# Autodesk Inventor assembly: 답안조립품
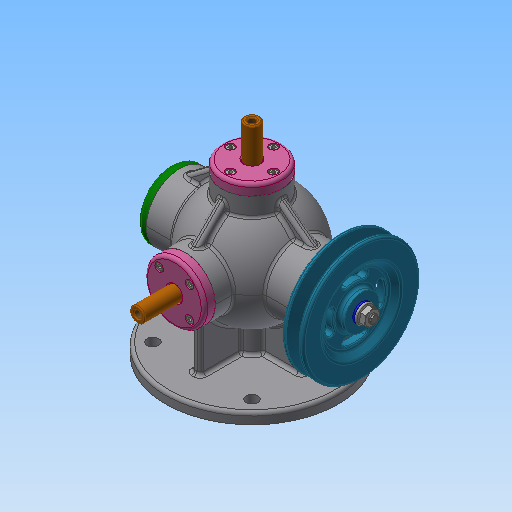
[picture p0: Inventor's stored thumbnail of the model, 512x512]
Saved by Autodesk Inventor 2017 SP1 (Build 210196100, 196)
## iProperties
Part Number: 답안조립품
Material: 일반
Document SubType Name: Assembly
Designer: MRC
Author: MRC
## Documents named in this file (17)
- C:\Users\MRC\Desktop\620909V1006\답안조립품.iam
- C:\Users\MRC\Desktop\620909V1006\본체.ipt
- C:\Users\MRC\Desktop\620909V1006\V-벨트풀리.ipt
- C:\Users\MRC\Desktop\620909V1006\가변스프링1.ipt
- C:\Users\MRC\Desktop\620909V1006\가변스프링2.ipt
- C:\Users\MRC\Desktop\620909V1006\너트-M8x1.ipt
- C:\Users\MRC\Desktop\620909V1006\뒤커버.ipt
- C:\Users\MRC\Desktop\620909V1006\베어링- 6202.ipt
- C:\Users\MRC\Desktop\620909V1006\본체커버.ipt
- C:\Users\MRC\Desktop\620909V1006\볼트 M4x0.7.ipt
- C:\Users\MRC\Desktop\620909V1006\슬라이드 커버.ipt
- C:\Users\MRC\Desktop\620909V1006\슬라이드.ipt
- C:\Users\MRC\Desktop\620909V1006\앞커버.ipt
- C:\Users\MRC\Desktop\620909V1006\오일실.ipt
- C:\Users\MRC\Desktop\620909V1006\와셔 8x17.ipt
- C:\Users\MRC\Desktop\620909V1006\축.ipt
- C:\Users\MRC\Desktop\620909V1006\키-4x4.ipt
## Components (20 placed, 4 different names)
1. V-벨트풀리:1
2. 가변스프링1:1
3. 가변스프링2:1
4. M4x0.7x12:17
5. M4x0.7x12:2
6. M4x0.7x12:5
7. M4x0.7x12:6
8. M4x0.7x12:7
9. M4x0.7x12:1
10. M4x0.7x12:8
11. M4x0.7x12:9
12. M4x0.7x12:10
13. M4x0.7x12:4
14. M4x0.7x12:11
15. M4x0.7x12:12
16. M4x0.7x12:13
17. M4x0.7x12:3
18. M4x0.7x12:14
19. M4x0.7x12:15
20. M4x0.7x12:16
